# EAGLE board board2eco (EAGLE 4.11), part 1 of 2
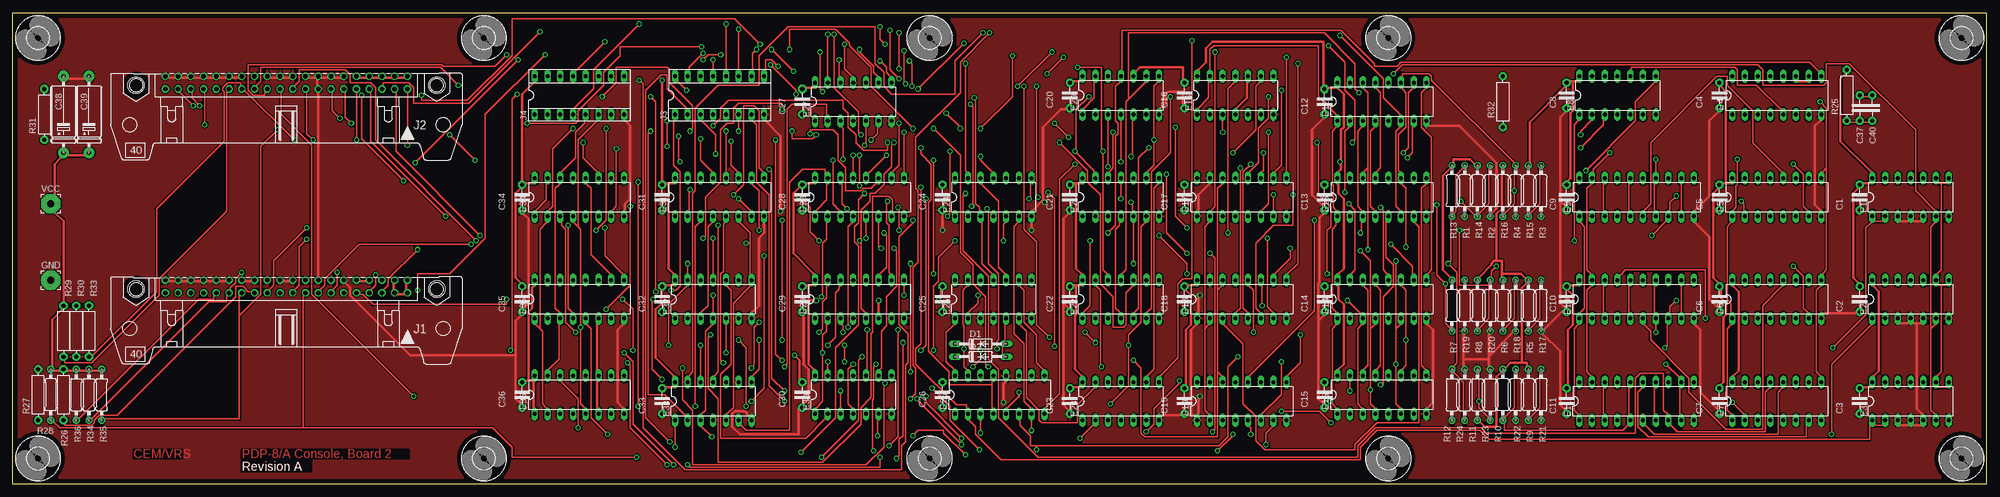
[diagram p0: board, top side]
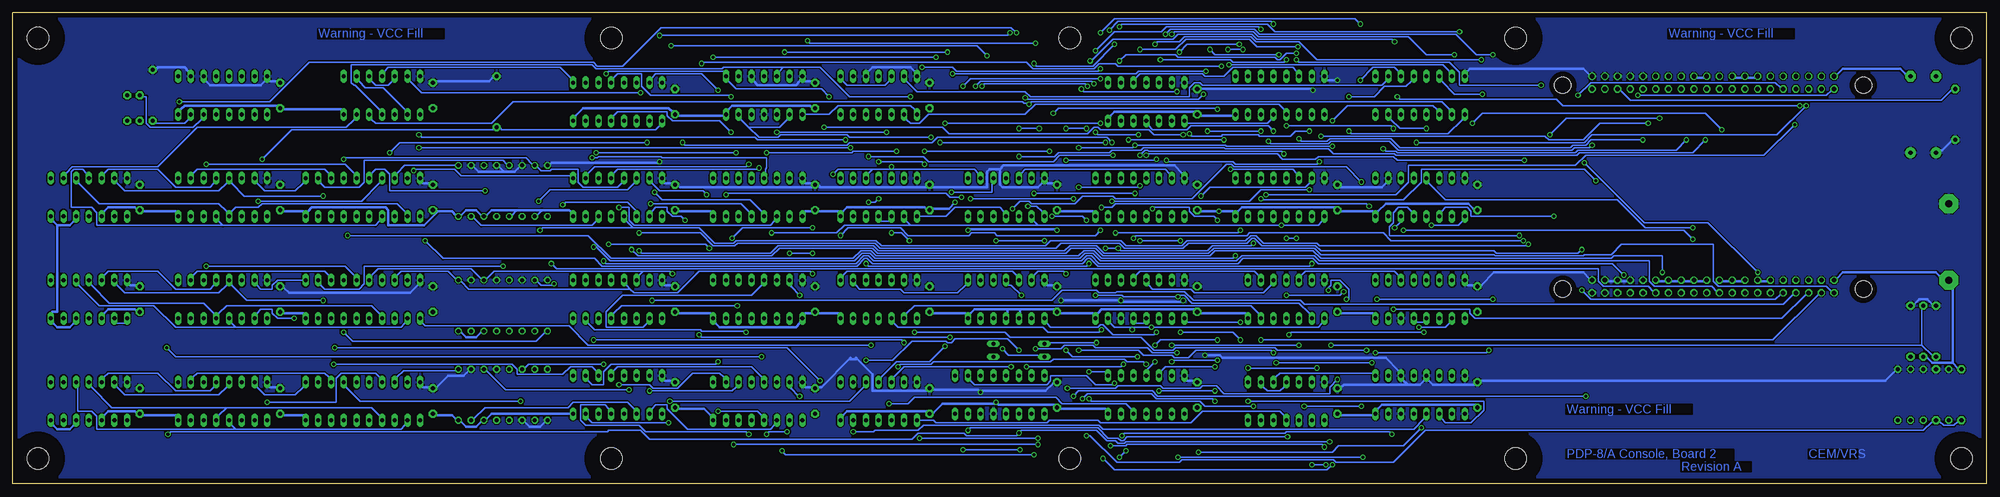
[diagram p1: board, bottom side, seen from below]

Size 393.7 x 93.98 mm. Coordinates in mm from the lower left corner, seen from the top.
Outline: 0,0 0,93.98 393.7,93.98 393.7,0 0,0
Copper layers (1*16): Top 0.035mm / dielectric 1.5mm / Bottom 0.035mm
Design rules "olimex8mil": minimum track width 10mil, minimum drill 24mil, track to track 8mil, track to pad 8mil, pad to pad 10mil, via to via 8mil, smd to smd 8mil, copper to edge 40mil, drill to drill 10mil, minimum pad ring 10mil, minimum via ring 8mil, stop-mask expansion 0mil, vias tented up to drill 0mil, thermal gap 10mil
Net classes: 1 Supply: width 0.508 mm

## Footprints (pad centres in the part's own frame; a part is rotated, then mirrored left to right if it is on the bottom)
C-5 = drill 0.813 pad 1.6 octagon: 1 -2.54,0; 2 2.54,0
E15-5 = drill 0.813 pad 2.159 round: + -7.62,0 | drill 0.813 pad 2.159 octagon: - 7.62,0
DO35-10 = drill 0.813 long: A 5.08,0; C -5.08,0
DIL14 = drill 0.813 long: 1 -7.62,-3.81; 2 -5.08,-3.81; 3 -2.54,-3.81; 4 0,-3.81; 5 2.54,-3.81; 6 5.08,-3.81; 7 7.62,-3.81; 8 7.62,3.81; 9 5.08,3.81; 10 2.54,3.81; 11 0,3.81; 12 -2.54,3.81; 13 -5.08,3.81; 14 -7.62,3.81
DIL16 = drill 0.813 long: 1 -8.89,-3.81; 2 -6.35,-3.81; 3 -3.81,-3.81; 4 -1.27,-3.81; 5 1.27,-3.81; 6 3.81,-3.81; 7 6.35,-3.81; 8 8.89,-3.81; 9 8.89,3.81; 10 6.35,3.81; 11 3.81,3.81; 12 1.27,3.81; 13 -1.27,3.81; 14 -3.81,3.81; 15 -6.35,3.81; 16 -8.89,3.81
DIL20 = drill 0.813 long: 1 -11.43,-3.81; 2 -8.89,-3.81; 3 -6.35,-3.81; 4 -3.81,-3.81; 5 -1.27,-3.81; 6 1.27,-3.81; 7 3.81,-3.81; 8 6.35,-3.81; 9 8.89,-3.81; 10 11.43,-3.81; 11 11.43,3.81; 12 8.89,3.81; 13 6.35,3.81; 14 3.81,3.81; 15 1.27,3.81; 16 -1.27,3.81; 17 -3.81,3.81; 18 -6.35,3.81; 19 -8.89,3.81; 20 -11.43,3.81
3,81/1,4 = drill 1.397 pad 3.81 octagon: 1 0,0
40H = drill 0.914 round: 1 -24.13,-1.27 | drill 0.914 octagon: 2 -24.13,1.27; 3 -21.59,-1.27; 4 -21.59,1.27; 5 -19.05,-1.27; 6 -19.05,1.27; 7 -16.51,-1.27; 8 -16.51,1.27; 9 -13.97,-1.27; 10 -13.97,1.27; 11 -11.43,-1.27; 12 -11.43,1.27; 13 -8.89,-1.27; 14 -8.89,1.27; 15 -6.35,-1.27; 16 -6.35,1.27; 17 -3.81,-1.27; 18 -3.81,1.27; 19 -1.27,-1.27; 20 -1.27,1.27; 21 1.27,-1.27; 22 1.27,1.27; 23 3.81,-1.27; 24 3.81,1.27; 25 6.35,-1.27; 26 6.35,1.27; 27 8.89,-1.27; 28 8.89,1.27; 29 11.43,-1.27; 30 11.43,1.27; 31 13.97,-1.27; 32 13.97,1.27; 33 16.51,-1.27; 34 16.51,1.27; 35 19.05,-1.27; 36 19.05,1.27; 37 21.59,-1.27; 38 21.59,1.27; 39 24.13,-1.27; 40 24.13,1.27 | hole 3.302: -29.972,0.533; 29.972,0.533
SOCKED-16 = drill 0.813 long: 1 -8.89,-3.81; 2 -6.35,-3.81; 3 -3.81,-3.81; 4 -1.27,-3.81; 5 1.27,-3.81; 6 3.81,-3.81; 7 6.35,-3.81; 8 8.89,-3.81; 9 8.89,3.81; 10 6.35,3.81; 11 3.81,3.81; 12 1.27,3.81; 13 -1.27,3.81; 14 -3.81,3.81; 15 -6.35,3.81; 16 -8.89,3.81
0207/10 = drill 0.813 octagon: 1 -5.08,0; 2 5.08,0
R-10 = drill 0.813 pad 1.6 octagon: 1 -5.08,0; 2 5.08,0
4,3 = hole 4.3: 0,0

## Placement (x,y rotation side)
C1  [C-5]  368.3,57.15 90 top
C2  [C-5]  368.3,36.83 90 top
C3  [C-5]  368.3,16.51 90 top
C4  [C-5]  340.36,77.47 90 top
C5  [C-5]  340.36,57.15 90 top
C6  [C-5]  340.36,36.83 90 top
C7  [C-5]  340.36,16.51 90 top
C8  [C-5]  309.88,77.47 90 top
C9  [C-5]  309.88,57.15 90 top
C10  [C-5]  309.88,36.83 90 top
C11  [C-5]  309.88,16.51 90 top
C12  [C-5]  261.62,76.2 90 top
C13  [C-5]  261.62,57.15 90 top
C14  [C-5]  261.62,36.83 90 top
C15  [C-5]  261.62,17.78 90 top
C16  [C-5]  233.68,77.47 90 top
C17  [C-5]  233.68,57.15 90 top
C18  [C-5]  233.68,36.83 90 top
C19  [C-5]  233.68,16.51 90 top
C20  [C-5]  210.82,77.47 90 top
C21  [C-5]  210.82,57.15 90 top
C22  [C-5]  210.82,36.83 90 top
C23  [C-5]  210.82,16.51 90 top
C24  [C-5]  185.42,57.15 90 top
C25  [C-5]  185.42,36.83 90 top
C26  [C-5]  185.42,17.78 90 top
C27  [C-5]  157.48,76.2 90 top
C28  [C-5]  157.48,57.15 90 top
C29  [C-5]  157.48,36.83 90 top
C30  [C-5]  157.48,17.78 90 top
C31  [C-5]  129.54,57.15 90 top
C32  [C-5]  129.54,36.83 90 top
C33  [C-5]  129.54,16.51 90 top
C34  [C-5]  101.6,57.15 90 top
C35  [C-5]  101.6,36.83 90 top
C36  [C-5]  101.6,17.78 90 top
C37  10  [C-5]  368.3,74.93 270 top
C38  6.8uf  [E15-5]  10.16,73.66 90 top
C39  6.8uf  [E15-5]  15.24,73.66 90 top
C40  47  [C-5]  370.84,74.93 270 top
D1  1N4148  [DO35-10]  193.04,27.94 0 top
D2  1N4148  [DO35-10]  193.04,25.4 0 top
E1  74LS95N  [DIL14]  378.46,57.15 0 top
E2  74LS95N  [DIL14]  378.46,36.83 0 top
E3  74LS95N  [DIL14]  378.46,16.51 0 top
E4  74LS123N  [DIL16]  351.79,77.47 0 top
E5  74LS175N  [DIL16]  351.79,57.15 0 top
E6  74LS175N  [DIL16]  351.79,36.83 0 top
E7  74LS175N  [DIL16]  351.79,16.51 0 top
E8  74LS00N  [DIL14]  320.04,77.47 0 top
E9  74S244N  [DIL20]  323.85,57.15 0 top
E10  74S244N  [DIL20]  323.85,36.83 0 top
E11  74S244N  [DIL20]  323.85,16.51 0 top
E12  74LS174N  [DIL16]  273.05,76.2 0 top
E13  74LS174N  [DIL16]  273.05,57.15 0 top
E14  74LS174N  [DIL16]  273.05,36.83 0 top
E15  74LS174N  [DIL16]  273.05,17.78 0 top
E16  74LS74N  [DIL14]  243.84,77.47 0 top
E17  74LS153N  [DIL16]  245.11,57.15 0 top
E18  74LS153N  [DIL16]  245.11,36.83 0 top
E19  74LS153N  [DIL16]  245.11,16.51 0 top
E20  74LS74N  [DIL14]  220.98,77.47 0 top
E21  74LS27N  [DIL14]  220.98,57.15 0 top
E22  74LS02N  [DIL14]  220.98,36.83 0 top
E23  7416N  [DIL14]  220.98,16.51 0 top
E24  74LS04N  [DIL14]  195.58,57.15 0 top
E25  74LS27N  [DIL14]  195.58,36.83 0 top
E26  74LS75N  [DIL16]  196.85,17.78 0 top
E27  7404N  [DIL14]  167.64,76.2 0 top
E28  74LS367N  [DIL16]  168.91,57.15 0 top
E29  74LS138N  [DIL16]  168.91,36.83 0 top
E30  74LS00N  [DIL14]  167.64,17.78 0 top
E31  74LS367N  [DIL16]  140.97,57.15 0 top
E32  74LS08N  [DIL14]  139.7,36.83 0 top
E33  74LS02N  [DIL14]  139.7,16.51 0 top
E34  74LS367N  [DIL16]  113.03,57.15 0 top
E35  74LS138N  [DIL16]  113.03,36.83 0 top
E36  74LS174N  [DIL16]  113.03,17.78 0 top
GND  [3,81/1,4]  7.62,40.64 0 top
J1  [40H]  54.61,39.37 180 top
J2  [40H]  54.61,80.01 180 top
J3  [SOCKED-16]  140.97,77.47 0 top
J4  [SOCKED-16]  113.03,77.47 0 top
R1  680  [0207/10]  289.56,58.42 90 top
R2  680  [0207/10]  294.64,58.42 90 top
R3  680  [0207/10]  304.8,58.42 90 top
R4  680  [0207/10]  299.72,58.42 90 top
R5  330  [0207/10]  302.26,35.56 90 top
R6  330  [0207/10]  297.18,35.56 90 top
R7  330  [0207/10]  287.02,35.56 90 top
R8  330  [0207/10]  292.1,35.56 90 top
R9  330  [0207/10]  302.26,17.78 90 top
R10  330  [0207/10]  297.18,17.78 90 top
R11  330  [0207/10]  292.1,17.78 270 top
R12  330  [0207/10]  287.02,17.78 270 top
R13  330  [0207/10]  287.02,58.42 90 top
R14  330  [0207/10]  292.1,58.42 90 top
R15  330  [0207/10]  302.26,58.42 90 top
R16  330  [0207/10]  297.18,58.42 90 top
R17  680  [0207/10]  304.8,35.56 90 top
R18  680  [0207/10]  299.72,35.56 90 top
R19  680  [0207/10]  289.56,35.56 90 top
R20  680  [0207/10]  294.64,35.56 90 top
R21  680  [0207/10]  304.8,17.78 90 top
R22  680  [0207/10]  299.72,17.78 90 top
R23  680  [0207/10]  294.64,17.78 270 top
R24  680  [0207/10]  289.56,17.78 270 top
R25  6K8  [R-10]  365.76,77.47 90 top
R26  180  [R-10]  10.16,17.78 270 top
R27  390  [R-10]  5.08,17.78 90 top
R28  1K  [0207/10]  7.62,17.78 90 top
R29  180  [R-10]  10.16,30.48 270 top
R30  390  [R-10]  12.7,30.48 270 top
R31  1K  [R-10]  6.35,73.66 90 top
R32  1K  [R-10]  297.18,76.2 270 top
R33  1K  [R-10]  15.24,30.48 270 top
R34  1K  [0207/10]  15.24,17.78 270 top
R35  1K  [0207/10]  17.78,17.78 270 top
R36  1K  [0207/10]  12.7,17.78 270 top
U$11  [4,3]  93.98,88.9 0 top
U$12  [4,3]  5.08,88.9 0 top
U$13  [4,3]  182.88,88.9 0 top
U$14  [4,3]  274.32,88.9 0 top
U$15  [4,3]  388.62,88.9 0 top
U$16  [4,3]  388.62,5.08 0 top
U$17  [4,3]  274.32,5.08 0 top
U$18  [4,3]  182.88,5.08 0 top
U$19  [4,3]  93.98,5.08 0 top
U$20  [4,3]  5.08,5.08 0 top
VCC  [3,81/1,4]  7.62,55.88 0 top

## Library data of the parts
C1-C37 C40 R25-R27 R29-R33 = discrete
C38 C39 R1-R24 R28 R34-R36 = rcl
D1 D2 = diode
E1-E36 = 74xx-us
GND VCC = wirepad
J1 J2 = con-harting-h
J3 J4 = ic-package
U$11-U$20 = holes

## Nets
ADDR0: E18.9 J3.9
ADDR1: E17.7 J3.12
ADDR2: E17.9 J3.10
ADRLTH\: E8.11 E12.9 E14.9
BEMA0: E27.10 J3.14
BEMA1: E27.8 J3.15
BEMA2: E27.12 J3.13
BFSW\: E28.9 J2.24
BKDTACNTL\: E28.3 J2.12
BOOTF\: E16.2 E16.6 E28.10
BPOK: E5.1 E6.1 E7.1 E12.1 E13.1 E14.1 E15.1 E16.1 E16.13 E20.1 E20.13 E23.10 J4.10 R32.2
BRUN: E24.6 E26.7 E32.4 E33.3 J4.12
BUS0: E11.3 E11.18 E14.3 E15.3 J1.34 R9.1 R21.2
BUS1: E10.3 E10.18 E14.13 E15.13 J1.36 R5.1 R17.2
BUS2: E9.3 E9.18 E12.6 E13.6 J1.38 R3.2 R15.1
BUS3: E11.5 E11.16 E14.4 E15.4 J1.40 R10.1 R22.2
BUS4: E10.5 E10.16 E14.14 E15.14 J1.20 R6.1 R18.2
BUS5: E9.5 E9.16 E12.11 E13.11 J1.22 R4.2 R16.1
BUS6: E11.7 E11.14 E14.6 E15.6 J1.8 R11.1 R23.2
BUS7: E10.7 E10.14 E12.3 E13.3 J1.6 R7.1 R19.2
BUS8: E9.7 E9.14 E12.13 E13.13 J1.12 R1.2 R12.1 R13.1 R24.2
BUS9: E11.9 E11.12 E14.11 E15.11 J1.10
BUS10: E10.9 E10.12 E12.4 E13.4 J1.16 R8.1 R20.2
BUS11: E9.9 E9.12 E12.14 E13.14 J1.14 R2.2 R14.1
BUSEN\: E34.13 J1.24
DEP\: E28.5 J2.20
DISP0: E34.14 E35.3 E36.15 J4.5
DISP1: E34.4 E35.2 E36.5 J4.6
DISP2: E34.2 E35.1 E36.2 J4.7
DISPINH: E16.9 E22.12 J4.4
DISPLAY0: E19.7 J3.7
DISPLAY1: E19.9 J3.11
DISPLAY2: E18.7 J3.6
DSPLTH\: E8.8 E13.9 E15.9
E30PIN8: E21.5 E21.11 E30.8
E35-Y4: E32.12 E35.11
EMA0\: E27.11 J1.30 R34.2
EMA1\: E27.9 J1.28 R35.2
EMA2\: E27.13 J1.32 R36.2
EMODE\: E1.6 E2.6 E3.6 E16.8 E22.6
ENT0: E3.13 E7.13 E11.8 E36.14
ENT1: E2.13 E6.13 E10.8 E36.4
ENT2: E1.13 E5.13 E9.8 E36.3
EXTPUL\: J4.9
FUN\: E24.3 E25.2 E25.11 J4.15
GATEENT\: E9.1 E10.1 E11.1 E21.6 E30.5
GATESR\: E9.19 E10.19 E11.19 E32.11
GND [Supply]: C1.1 C2.1 C3.1 C4.1 C5.1 C6.1 C7.1 C8.1 C9.1 C10.1 C11.1 C12.1 C13.1 C14.1 C15.1 C16.1 C17.1 C18.1 C19.1 C20.1 C21.1 C22.1 C23.1 C24.1 C25.1 C26.1 C27.1 C28.1 C29.1 C30.1 C31.1 C32.1 C33.1 C34.1 C35.1 C36.1 C38.- C39.- E1.3 E1.4 E1.5 E1.7 E2.3 E2.4 E2.5 E2.7 E3.3 E3.4 E3.5 E3.7 E4.8 E5.8 E6.8 E7.8 E8.7 E9.10 E10.10 E11.10 E12.8 E13.8 E14.8 E15.8 E16.7 E17.1 E17.8 E17.15 E18.1 E18.8 E18.15 E19.1 E19.8 E19.15 E20.7 E21.7 E22.7 E23.7 E24.7 E25.3 E25.4 E25.7 E26.12 E27.7 E28.8 E29.8 E30.7 E31.8 E32.7 E33.7 E34.8 E35.8 E36.8 GND.1 J1.11 J1.13 J1.15 J1.17 J1.19 J1.21 J1.23 J1.25 J1.27 J1.29 J1.31 J1.33 J1.35 J1.37 J1.39 J2.11 J2.13 J2.15 J2.16 J2.17 J2.19 J2.21 J2.23 J2.25 J2.27 J2.29 J2.31 J2.33 J2.35 J2.37 J2.39 J3.8 J4.8 R1.1 R2.1 R3.1 R4.1 R17.1 R18.1 R19.1 R20.1 R21.1 R22.1 R23.1 R24.1 R27.2 R30.2
IND1\: E28.7 E34.3 J2.8
IND2\: E34.5 J2.4
INIT\: E31.9 J2.34
KEY-F\: E26.4 E26.13 E27.5 J4.3
KEYCNTL\: E31.13 J2.10
KEYSTB: E8.5 E24.1 J4.2
KEYSTB\: E16.11 E21.2 E24.2 E31.1 E33.9 E33.11
KFUN0\: E3.1 E3.2 E26.2 J3.3
KFUN1\: E2.1 E2.2 E26.3 J3.2
KFUN2\: E1.1 E1.2 E26.6 J3.1
LAENAB\: E23.2 J2.22
LDSR: E5.9 E6.9 E7.9 E33.13
MAEN\: E23.8 J2.32
MALC\: E28.11 J2.36
MCLOCK\: E33.2 J4.1
MD\: E34.7 J2.18
MEMSTART\: E23.12 J2.26
MH0: E8.13 E20.9 E22.11
MH0\: E8.2 E8.9 E20.8 E20.12 E21.9
MPXA: E17.14 E18.14 E19.14 J4.14
MPXB: E17.2 E18.2 E19.2 J4.13
MSIRDIS\: E31.11 J2.2
N$1: E2.12 E6.12 E10.6
N$2: E1.12 E5.12 E9.6
N$3: E1.10 E5.4 E9.2
N$4: E1.11 E5.5 E9.4
N$5: E2.10 E6.4 E10.2
N$6: E2.11 E6.5 E10.4
N$7: E3.12 E7.12 E11.6
N$8: E3.10 E7.4 E11.2
N$9: E3.11 E7.5 E11.4
N$10: E15.2 E19.3
N$11: E15.5 E19.5
N$12: E15.7 E19.4
N$13: E15.10 E19.6
N$14: E15.12 E19.13
N$15: E15.15 E19.11
N$16: E13.2 E19.12
N$17: E13.5 E19.10
N$18: E13.7 E18.3
N$19: E13.10 E18.5
N$20: E13.12 E18.4
N$21: E13.15 E18.6
N$22: E14.2 E18.13
N$23: E14.5 E18.11
N$24: E14.7 E18.12
N$25: E14.10 E18.10
N$26: E12.15 E17.10
N$27: E12.12 E17.12
N$28: E12.10 E17.11
N$29: E12.7 E17.13
N$30: E14.15 E17.5
N$31: E14.12 E17.3
N$32: E12.2 E17.4
N$33: E12.5 E17.6
N$34: E16.3 E21.12
N$35: E21.1 E24.4
N$36: E22.10 E29.4 E29.5 E31.15
N$37: E22.13 E30.4
N$38: E8.3 E22.5
N$39: E22.3 E33.1
N$40: E22.2 E32.6
N$41: E4.9 E20.11 E22.1
N$42: E22.8 E25.12
N$43: D1.C E31.5
N$44: E24.8 E32.5
N$45: D2.C E31.3
N$46: E33.10 E36.9
N$47: E23.11 E24.10
N$48: E29.15 E33.8
N$49: E26.10 E29.1
N$50: E25.13 E26.15 E27.3 E29.2 E30.1
N$51: E25.1 E26.16 E29.3
N$52: E21.3 E21.4 E22.4
N$53: E22.9 E25.8
N$54: D1.A D2.A E25.5
N$55: E28.4 E29.7 E30.10 E32.1
N$56: E28.2 E29.9 E32.2
N$57: E29.10 E31.2
N$58: E29.11 E31.10
N$59: E29.12 E32.9
N$60: E29.13 E30.2 E32.10
N$61: E29.14 E33.12
N$62: E23.1 E33.4
N$63: E7.15 E11.11
N$64: E7.10 E11.13
N$65: E7.7 E11.15
N$66: E7.2 E11.17
N$67: E27.6 E30.13
N$68: E28.14 E30.11
N$69: E31.4 E32.3
N$70: E30.6 E34.1 E34.15 E35.4 E35.5
N$71: E28.6 E30.9 E31.6 E32.8 E33.5
N$72: E34.12 E35.10
N$73: E34.6 E35.9
N$74: E27.4 E31.12
N$75: E4.5 E8.10 E8.12
N$76: E30.3 E31.14
N$77: E27.2 E30.12
N$78: E23.13 E25.6
N$79: E6.15 E10.11
N$80: E6.10 E10.13
N$81: E6.7 E10.15
N$82: E6.2 E10.17
N$83: E5.15 E9.11
N$84: E5.10 E9.13
N$85: E5.2 E9.17
N$86: E5.7 E9.15
N$87: E21.8 E23.9
N$88: C37.1 C40.1 E4.6
N$89: C37.2 C40.2 E4.7 R25.1
N$93: E20.4 E26.8
N$94: E25.9 E26.9
NUM: E8.4 E16.12 E21.13 J4.11
NUMCLK: E1.8 E1.9 E2.8 E2.9 E3.8 E3.9 E8.6
PANLOCK: E24.12 E25.10 E28.1 E28.15 E33.6
PANLOCK\: E24.13 J2.6 R31.2
POWCK: E24.11 J2.28 R33.2
PULSELOADADD\: E31.7 J2.40
RUN\: E24.5 J1.18 R28.1
SHLT\: E27.1 J3.5
SINGSTEP\: E28.13 J2.14
SRDATA\: E8.1 E32.13 J2.30 R29.2 R30.1
STATE\: E34.11 J2.38
STHIS\: E20.2 J3.4
THIS: E20.5 E28.12
TS1\: E20.3 E21.10 E24.9 J1.26 R26.2 R27.1
VCC [Supply]: C1.2 C2.2 C3.2 C4.2 C5.2 C6.2 C7.2 C8.2 C9.2 C10.2 C11.2 C12.2 C13.2 C14.2 C15.2 C16.2 C17.2 C18.2 C19.2 C20.2 C21.2 C22.2 C23.2 C24.2 C25.2 C26.2 C27.2 C28.2 C29.2 C30.2 C31.2 C32.2 C33.2 C34.2 C35.2 C36.2 C38.+ C39.+ E1.14 E2.14 E3.14 E4.10 E4.11 E4.16 E5.16 E6.16 E7.16 E8.14 E9.20 E10.20 E11.20 E12.16 E13.16 E14.16 E15.16 E16.4 E16.10 E16.14 E17.16 E18.16 E19.16 E20.10 E20.14 E21.14 E22.14 E23.14 E24.14 E25.14 E26.5 E27.14 E28.16 E29.6 E29.16 E30.14 E31.16 E32.14 E33.14 E34.10 E34.16 E35.6 E35.16 E36.1 E36.6 E36.11 E36.13 E36.16 J1.1 J1.2 J1.3 J1.4 J1.5 J1.7 J1.9 J2.1 J2.3 J2.5 J2.7 J2.9 J3.16 J4.16 R5.2 R6.2 R7.2 R8.2 R9.2 R10.2 R11.2 R12.2 R13.2 R14.2 R15.2 R16.2 R25.2 R26.1 R28.2 R29.1 R31.1 R32.1 R33.1 R34.1 R35.1 R36.1 VCC.1

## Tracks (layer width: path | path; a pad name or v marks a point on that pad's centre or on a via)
ADDR0  (via drill 0.61)
  Top 0.254: v256.29,83.82 256.29,43.94 254.25,41.91 E18.9 | v152.65,83.31 151.38,84.58 150.11,84.58 150.11,82.55 J3.9
  Bottom 0.254: v256.29,83.82 256.03,84.07 191.52,84.07 190.25,82.8 178.05,82.8 177.04,83.82 173.74,83.82 173.23,83.31 v152.65,83.31
ADDR1  (via drill 0.61)
  Top 0.254: v251.46,57.66 251.46,54.61 E17.7 | v204.47,57.15 204.22,57.4 v204.22,79.25 | v176.78,80.77 175.01,82.55 v175.01,90.42 | v142.24,91.69 142.24,82.55 J3.12
  Bottom 0.254: v251.46,57.66 251.21,57.91 207.52,57.91 206.76,57.15 v204.47,57.15 | v204.22,79.25 202.69,80.77 v176.78,80.77 | v175.01,90.42 173.23,92.2 142.75,92.2 v142.24,91.69
ADDR2  (via drill 0.61)
  Top 0.254: v254,85.09 254,62.23 E17.9 | v206.25,81.79 v209.55,85.09 | v155.7,82.3 v151.38,86.61 | v148.34,86.61 147.57,85.85 147.57,82.55 J3.10
  Bottom 0.254: v209.55,85.09 v254,85.09 | v206.25,81.79 169.67,81.79 169.16,82.3 v155.7,82.3 | v151.38,86.61 v148.34,86.61
ADRLTH\
  Top 0.254: E14.9 282.19,41.91 282.96,42.67 282.96,69.09 280.92,71.12 280.92,77.98 281.69,78.74 E12.9
  Bottom 0.254: E8.11 319.53,82.3 318.77,83.06 284.48,83.06 282.45,81.03 E12.9
BEMA0
  Bottom 0.254: E27.10 169.67,81.03 168.91,81.79 156.46,81.79 155.96,81.28 152.15,81.28 150.37,83.06 138.43,83.06 137.67,82.3 J3.14
BEMA1  (via drill 0.61)
  Top 0.254: v172.97,84.33 174.24,83.06 174.24,82.04 175.01,81.28 E27.8 | v137.67,85.85 134.87,83.06 134.87,82.55 J3.15
  Bottom 0.254: v172.97,84.33 171.7,85.6 161.8,85.6 161.29,85.09 141.99,85.09 141.48,84.58 140.97,84.58 139.7,85.85 v137.67,85.85
BEMA2  (via drill 0.61)
  Top 0.254: v139.7,84.58 139.7,82.55 J3.13 | v164.85,84.58 164.85,81.28 E27.12
  Bottom 0.254: v139.7,84.58 140.21,84.07 150.37,84.07 150.88,84.58 v164.85,84.58
BFSW\  (via drill 0.61)
  Top 0.254: v177.8,70.1 177.8,62.23 E28.9 | v169.16,69.6 168.66,70.1 168.66,74.17 163.83,78.99 v163.83,89.66 | v98.55,85.6 96.27,83.31 85.85,83.31 85.6,83.57 46.99,83.57 46.99,78.49 48.01,77.47 50.29,77.47 50.29,78.49 J2.24
  Bottom 0.254: v177.8,70.1 177.29,69.6 v169.16,69.6 | v163.83,89.66 162.81,90.68 146.05,90.68 145.03,89.66 105.92,89.66 101.85,85.6 v98.55,85.6
BKDTACNTL\  (via drill 0.61)
  Top 0.254: v163.58,64.52 163.58,55.88 164.85,54.61 E28.3 | v133.1,64.26 132.84,64.52 v132.84,69.34 | v67.56,71.88 66.29,73.15 66.29,78.23 J2.12
  Bottom 0.254: v163.58,64.52 163.32,64.26 150.37,64.26 149.86,63.75 133.6,63.75 v133.1,64.26 | v132.84,69.34 88.14,69.34 87.38,68.58 80.52,68.58 77.22,71.88 v67.56,71.88
BOOTF\  (via drill 0.61)
  Top 0.254: v176.78,71.88 176.78,63.5 175.51,62.23 E28.10 | v210.57,69.09 v207.77,71.88
  Bottom 0.254: v207.77,71.88 v176.78,71.88 | v210.57,69.09 226.82,69.09 227.33,69.6 240.54,69.6 241.05,69.09 244.86,69.09 246.89,71.12 | 246.89,71.12 248.41,72.64 E16.6 | 246.89,71.12 240.79,71.12 239.27,72.64 E16.2
BPOK  (via drill 0.61)
  Top 0.254: E16.1 236.47,74.93 238.51,76.96 238.51,80.01 E16.13 238.76,82.55 238.76,86.61 239.52,87.38 260.35,87.38 260.35,77.22 263.91,73.66 E12.1 263.91,71.12 263.14,70.36 263.14,59.69 263.4,59.44 263.4,55.12 263.91,54.61 E13.1 263.91,52.07 263.91,51.56 263.14,50.8 263.14,35.05 263.91,34.29 E14.1 263.91,31.75 263.14,30.99 263.14,16.51 | E20.1 213.61,74.93 215.65,76.96 215.65,80.01 E20.13 | 263.14,16.51 263.14,16 263.91,15.24 E15.1 | 263.14,16.51 v262.64,16.51 | E7.1 342.65,13.97 341.88,14.73 341.88,30.99 342.65,31.75 E6.1 342.65,34.29 342.65,36.07 341.88,36.83 341.88,51.31 342.65,52.07 E5.1 343.15,54.61 343.66,55.12 343.66,59.44 343.92,59.69 v343.92,64.77
  Bottom 0.254: J4.10 119.89,80.26 120.65,79.5 156.46,79.5 156.97,80.01 157.99,80.01 159,78.99 159,77.22 190.75,77.22 191.77,78.23 213.36,78.23 215.39,80.26 E20.13 | E16.1 235.71,73.66 230.89,73.66 229.11,75.44 214.63,75.44 213.87,74.68 E20.1 | v262.64,16.51 226.82,16.51 224.03,19.3 E23.10 | E12.1 264.67,71.37 265.43,70.61 296.16,70.61 296.42,70.87 R32.2 297.69,70.61 338.07,70.61 v343.92,64.77
BRUN  (via drill 0.61)
  Top 0.254: E24.6 200.41,52.07 199.64,51.31 199.64,29.97 201.68,27.94 201.68,16.51 202.95,15.24 E26.7 203.2,12.7 v203.2,10.67 | v127.25,77.22 128.27,76.2 v128.27,38.35 | v139.7,37.59 139.7,34.29 E32.4 139.45,31.75 138.18,30.48 138.18,14.73 137.41,13.97 E33.3 137.41,11.43 v139.45,9.4
  Bottom 0.254: v127.25,77.22 122.17,77.22 120.14,79.25 115.82,79.25 114.81,80.26 J4.12 | v128.27,38.35 129.03,37.59 v139.7,37.59 | v203.2,10.67 202.69,11.18 177.29,11.18 175.26,9.14 173.23,9.14 172.72,8.64 172.21,8.64 171.45,9.4 v139.45,9.4
BUS0  (via drill 0.61)
  Top 0.254: E11.3 317.25,13.97 317.25,19.05 E11.18 | R9.1 302.51,13.21 304.55,15.24 304.55,22.35 R21.2 | E15.3 268.99,15.24 268.22,16 268.22,30.99 268.99,31.75 E14.3 268.73,34.04 v266.19,36.58
  Bottom 0.254: E11.18 316.99,21.34 315.72,22.61 305.31,22.61 R21.2 | v266.19,36.58 186.44,36.58 184.4,38.61 177.55,38.61 177.04,38.1 173.74,38.1 173.48,38.35 160.02,38.35 158.24,36.58 136.91,36.58 136.14,35.81 40.64,35.81 38.61,37.85 J1.34 | R9.1 301.75,12.95 299.47,15.24 282.96,15.24 281.94,16.26 271.02,16.26 269.75,14.99 E15.3
BUS1  (via drill 0.61)
  Top 0.254: E10.3 317.25,34.29 317.25,39.37 E10.18 | R5.1 302.51,30.99 304.55,33.02 304.55,40.13 R17.2 | E15.13 272.03,22.86 272.8,23.62 272.8,38.61 272.03,39.37 E14.13 | v118.36,34.8 123.19,39.62 v123.19,55.37 | v176.53,55.12 176.78,54.86 v176.78,50.55 | v228.6,49.53 234.19,43.94 v234.19,41.91
  Bottom 0.254: E10.18 316.99,41.66 316.23,42.42 306.83,42.42 305.31,40.89 R17.2 304.29,40.39 302.77,38.86 270.51,38.86 | v118.36,34.8 103.12,34.8 103.12,34.04 102.11,33.02 40.89,33.02 36.07,37.85 J1.36 | v123.19,55.37 123.7,55.88 173.74,55.88 174.5,55.12 v176.53,55.12 | v176.78,50.55 177.8,49.53 197.36,49.53 197.87,50.04 202.44,50.04 202.95,49.53 215.14,49.53 216.66,51.05 227.08,51.05 v228.6,49.53 | v234.19,41.91 234.7,42.42 256.79,42.42 261.11,38.1 269.75,38.1 270.51,38.86 | 270.51,38.86 271.27,39.62 E14.13
BUS2  (via drill 0.61)
  Top 0.254: E9.3 317.25,54.61 317.25,59.69 E9.18 | R15.1 302.51,53.85 304.55,55.88 304.55,62.99 R3.2 | E13.6 276.61,54.61 275.84,55.37 275.84,70.36 276.61,71.12 E12.6 276.61,73.66 273.3,76.96 273.3,80.77 v264.67,89.41 | v144.78,28.7 146.3,27.18 v146.3,15.49 | v179.07,17.02 180.09,18.03 180.09,23.11 179.58,23.62 179.58,43.18 180.59,44.2 180.59,58.42 180.09,58.93 180.09,69.09 188.98,77.98 188.98,84.07 v194.82,89.92
  Bottom 0.254: E9.18 316.99,61.98 315.47,63.5 305.31,63.5 R3.2 | v144.78,28.7 42.67,28.7 33.53,37.85 J1.38 | v146.3,15.49 155.96,15.49 156.97,16.51 178.56,16.51 v179.07,17.02 | v194.82,89.92 195.33,89.41 v264.67,89.41 | R15.1 301.75,53.09 300.23,51.56 278.13,51.56 277.37,52.32 E13.6
BUS3  (via drill 0.61)
  Top 0.254: E11.16 322.33,19.05 322.33,13.97 E11.5 322.07,11.68 321.06,10.67 297.43,10.67 297.43,12.19 R10.1 297.43,13.21 299.47,15.24 299.47,22.35 R22.2 | 270.76,30.99 v270.76,18.8 270.76,16 271.53,15.24 E15.4 | 270.76,30.99 271.53,31.75 E14.4 | v268.73,46.48 270.76,44.45 270.76,30.99
  Bottom 0.254: v268.73,46.48 268.22,45.97 242.57,45.97 241.05,47.5 222,47.5 220.98,46.48 183.9,46.48 182.88,47.5 177.55,47.5 176.02,45.97 155.19,45.97 154.18,46.99 134.11,46.99 132.84,45.72 98.3,45.72 98.04,45.47 80.52,45.47 80.26,45.72 74.93,45.72 72.9,47.75 54.61,47.75 54.61,40.39 53.59,39.37 32,39.37 30.99,38.35 J1.40 | v270.76,18.8 295.4,18.8 299.21,22.61 R22.2
BUS4  (via drill 0.61)
  Top 0.254: E10.5 322.33,34.29 322.33,39.37 E10.16 | R6.1 297.43,30.99 299.47,33.02 299.47,40.13 R18.2 | E15.14 269.49,22.86 270.26,23.62 270.26,38.61 269.49,39.37 E14.14 | v58.67,48.77 57.15,47.24 57.15,39.62 56.13,38.61 J1.20 | v116.33,50.55 118.36,52.58 v118.36,70.87 | v139.7,71.37 141.22,72.9 141.22,74.93 142.75,76.45 165.61,76.45 165.61,74.93 166.62,73.91 166.62,71.12 168.15,69.6 168.15,68.07 169.67,66.55 174.5,66.55 v174.5,68.07 | v260.1,68.07 260.35,67.82 260.35,57.66 262.89,55.12 262.89,51.31 262.13,50.55 v262.13,41.91
  Bottom 0.254: E10.16 322.07,41.66 320.8,42.93 302.26,42.93 300.23,40.89 R18.2 299.21,40.89 297.69,42.42 267.97,42.42 | v58.67,48.77 60.45,50.55 v116.33,50.55 | v118.36,70.87 118.87,71.37 v139.7,71.37 | v174.5,68.07 175.51,69.09 209.3,69.09 210.31,68.07 226.82,68.07 227.33,67.56 259.59,67.56 v260.1,68.07 | v262.13,41.91 262.64,42.42 267.97,42.42 | 267.97,42.42 268.73,41.66 E14.14
BUS5  (via drill 0.61)
  Top 0.254: E9.5 322.33,54.61 322.33,59.69 E9.16 | R16.1 297.43,53.85 299.47,55.88 v299.47,58.42 299.47,62.99 R4.2 299.47,64.01 282.96,80.52 282.96,81.28 282.45,81.79 277.11,81.79 277.11,81.28 E12.11 277.11,78.74 277.88,77.98 277.88,71.12 276.35,69.6 276.35,62.48 276.61,62.23 E13.11 277.11,59.69 277.88,58.93 v277.88,47.24
  Bottom 0.254: v299.47,58.42 318.52,58.42 318.52,61.72 319.53,62.74 321.31,62.74 322.07,61.98 E9.16 | v277.88,47.24 277.37,47.24 274.57,44.45 225.81,44.45 224.28,45.97 222.76,45.97 221.74,44.96 180.85,44.96 179.83,45.97 178.31,45.97 176.78,44.45 149.61,44.45 148.59,45.47 134.11,45.47 133.1,44.45 67.31,44.45 67.31,40.39 66.29,39.37 54.86,39.37 53.85,38.35 J1.22
BUS6  (via drill 0.61)
  Top 0.254: E11.7 327.41,13.97 327.41,19.05 E11.14 | R23.2 294.39,13.21 292.35,15.24 v292.35,16.51 292.35,22.35 R11.1 | 275.84,30.99 v275.84,23.88 275.84,16 276.61,15.24 E15.6 | 275.84,30.99 276.61,31.75 E14.6 | v72.39,41.66 72.39,39.62 71.37,38.61 J1.8 | v275.84,44.45 275.84,30.99
  Bottom 0.254: v292.35,16.51 324.36,16.51 327.15,19.3 E11.14 | v72.39,41.66 74.68,43.94 133.35,43.94 134.37,44.96 148.34,44.96 149.35,43.94 177.04,43.94 178.56,45.47 179.58,45.47 180.59,44.45 222,44.45 223.01,45.47 224.03,45.47 225.55,43.94 275.34,43.94 v275.84,44.45 | v275.84,23.88 290.83,23.88 291.59,23.11 R11.1
BUS7  (via drill 0.61)
  Top 0.254: E10.14 327.41,39.37 327.41,34.29 E10.7 327.66,31.75 v327.66,30.23 | R7.1 286.77,30.99 285.75,32 v285.75,39.88 285.5,40.13 283.97,41.66 v283.97,55.63 | E12.3 268.99,71.12 268.22,70.36 268.22,55.37 268.99,54.61 E13.3 268.99,52.07 268.99,50.29 v268.73,50.04 | v80.77,46.74 74.93,40.89 74.93,39.62 73.91,38.61 J1.6
  Bottom 0.254: v285.75,39.88 286,39.62 288.29,39.62 289.05,40.39 R19.2 | v327.66,30.23 325.88,28.45 289.31,28.45 287.53,30.23 R7.1 | v80.77,46.74 81.53,45.97 97.79,45.97 98.3,46.48 132.84,46.48 133.86,47.5 144.53,47.5 146.05,49.02 146.56,49.02 147.57,48.01 159.26,48.01 160.27,46.99 171.96,46.99 172.97,48.01 184.66,48.01 185.67,46.99 220.73,46.99 221.74,48.01 249.17,48.01 249.68,47.5 254,47.5 256.54,50.04 v268.73,50.04 | v283.97,55.63 283.46,56.13 271.02,56.13 269.49,54.61 E13.3
BUS8  (via drill 0.61)
  Top 0.254: E13.13 272.03,62.23 272.8,62.99 272.8,77.98 272.03,78.74 E12.13 | R24.2 289.31,13.21 289.31,20.32 287.27,22.35 R12.1 287.27,23.37 288.04,24.13 288.04,42.16 286.51,43.69 v286.26,43.94 286.77,44.45 286.77,52.83 R13.1 287.27,53.85 287.78,54.36 287.78,61.47 289.31,62.99 R1.2 | E9.7 327.41,54.61 327.41,59.69 E9.14 327.66,62.23 v327.66,64.77
  Bottom 0.254: v286.26,43.94 285.24,42.93 77.47,42.93 77.47,40.39 76.45,39.37 67.56,39.37 66.55,38.35 J1.12 | v327.66,64.77 327.41,65.02 291.34,65.02 290.07,63.75 R1.2 289.05,63.25 288.29,62.48 286.51,62.48 286.26,62.74 280.92,62.74 280.92,60.2 279.91,59.18 273.05,59.18 272.29,59.94 E13.13
BUS9  (via drill 0.61)
  Top 0.254: E11.9 332.49,13.97 332.49,19.05 E11.12 332.23,21.34 v329.69,23.88 | E14.11 277.11,39.37 277.88,38.61 v277.88,28.7 277.88,23.62 277.11,22.86 E15.11 | v98.55,36.83 98.55,35.81 71.88,35.81 69.85,37.85 69.09,37.85 J1.10 | v121.67,36.83 123.7,34.8 v123.7,26.67 | v215.9,28.19 v213.87,30.23
  Bottom 0.254: v329.69,23.88 294.13,23.88 293.12,22.86 293.12,21.84 283.97,21.84 282.45,23.37 278.13,23.37 277.37,22.61 E15.11 | v121.67,36.83 v98.55,36.83 | v123.7,26.67 141.48,26.67 141.99,27.18 161.8,27.18 162.31,26.67 166.12,26.67 168.66,29.21 194.82,29.21 195.83,30.23 v213.87,30.23 | v215.9,28.19 216.41,28.7 v277.88,28.7
BUS10  (via drill 0.61)
  Top 0.254: E10.9 332.74,34.29 332.74,39.37 E10.12 | 294.39,39.62 294.39,40.13 R20.2 294.89,41.15 294.89,42.42 v295.91,43.43 | 294.39,39.62 294.39,33.02 292.35,30.99 R8.1 | E13.4 271.53,54.61 270.76,55.37 270.76,70.36 271.53,71.12 E12.4 | v91.44,47.75 69.09,47.75 62.23,40.89 62.23,39.62 61.21,38.61 J1.16 | 294.39,39.62 288.54,39.62 v288.54,50.55
  Bottom 0.254: v295.91,43.43 323.6,43.43 323.6,39.88 324.61,38.86 331.47,38.86 332.23,39.62 E10.12 | v91.44,47.75 91.69,47.5 133.1,47.5 133.6,48.01 144.27,48.01 145.8,49.53 146.81,49.53 147.83,48.51 159.51,48.51 160.53,47.5 171.7,47.5 172.72,48.51 186.69,48.51 187.71,47.5 220.47,47.5 221.49,48.51 249.43,48.51 249.94,48.01 253.75,48.01 256.79,51.05 270,51.05 | 270,51.05 271.27,52.32 E13.4 | v288.54,50.55 288.04,51.05 270,51.05
BUS11  (via drill 0.61)
  Top 0.254: E9.9 332.74,54.61 332.74,59.69 E9.12 | R2.2 294.39,62.99 294.39,55.88 292.35,53.85 R14.1 291.59,53.59 v288.8,56.39 | 270.26,62.99 269.49,62.23 E13.14 | 270.26,62.99 270.26,77.98 269.49,78.74 E12.14 | v64.77,42.16 64.77,39.62 63.75,38.61 J1.14 | v270.26,46.74 270.26,62.99
  Bottom 0.254: E9.12 332.23,59.94 331.47,59.18 324.61,59.18 323.6,60.2 323.6,64.52 295.91,64.52 295.15,63.75 R2.2 | v64.77,42.16 64.77,45.47 74.42,45.47 74.93,44.96 132.84,44.96 134.37,46.48 153.92,46.48 154.94,45.47 176.28,45.47 177.8,46.99 182.63,46.99 183.64,45.97 221.23,45.97 222.25,46.99 240.79,46.99 242.32,45.47 268.99,45.47 v270.26,46.74 | v288.8,56.39 286.51,58.67 271.02,58.67 269.75,59.94 E13.14
BUSEN\  (via drill 0.61)
  Top 0.254: v58.67,51.05 52.07,44.45 52.07,39.62 51.05,38.61 J1.24
  Bottom 0.254: v58.67,51.05 68.07,51.05 73.66,56.64 107.95,56.64 111.25,59.94 E34.13
DEP\  (via drill 0.61)
  Top 0.254: v170.18,49.02 170.18,52.07 E28.5 | v92.46,48.51 72.39,68.58 72.39,78.99 71.37,80.01 67.31,80.01 67.31,81.53 66.29,82.55 57.15,82.55 57.15,80.26 56.13,79.25 J2.20
  Bottom 0.254: v170.18,49.02 169.67,49.53 147.57,49.53 147.07,50.04 120.4,50.04 118.87,48.51 v92.46,48.51
DISP0
  Top 0.254: E36.15 106.93,22.86 108.97,24.89 108.97,31.75 E35.3 108.97,34.29 108.2,35.05 108.2,58.93 108.97,59.69 E34.14 109.47,62.23 112.27,65.02 112.27,70.1 114.05,71.88 114.05,72.39 J4.5
DISP1  (via drill 0.61)
  Top 0.254: 112.78,51.31 112.01,52.07 E34.4 | 112.78,51.31 113.28,50.8 v113.28,31.24 113.28,16 114.05,15.24 E36.5 | 112.78,51.31 112.78,68.58 116.59,72.39 J4.6
  Bottom 0.254: v113.28,31.24 107.95,31.24 107.19,32 E35.2
DISP2  (via drill 0.61)
  Top 0.254: 105.16,30.99 105.66,30.48 105.66,16 106.43,15.24 E36.2 | 105.16,30.99 104.39,31.75 E35.1 | 105.16,30.99 105.16,50.8 106.43,52.07 E34.2 106.93,54.61 107.7,55.37 107.7,66.8 v111.76,70.87
  Bottom 0.254: v111.76,70.87 117.09,70.87 118.87,72.64 J4.7
DISPINH  (via drill 0.61)
  Top 0.254: v243.33,66.04 247.9,70.61 247.9,79.25 248.67,80.01 E16.9 | E22.12 218.19,41.91 217.42,42.67 v217.42,66.29 217.17,66.55 217.17,83.06 v212.34,83.06 | v124.97,91.69 115.82,82.55 115.82,78.74 112.01,74.93 J4.4 | v176.78,82.8 v176.78,89.92
  Bottom 0.254: v217.42,66.29 226.06,66.29 226.31,66.04 v243.33,66.04 | v124.97,91.69 125.98,92.71 173.99,92.71 v176.78,89.92 | v176.78,82.8 177.29,82.3 205.49,82.3 206.25,83.06 v212.34,83.06
DISPLAY0  (via drill 0.61)
  Top 0.254: v249.94,7.87 249.94,10.16 251.21,11.43 E19.7 | v189.23,7.87 180.34,16.76 v180.34,17.02 | v153.92,16.51 150.88,19.56 150.88,57.66 148.34,60.2 148.34,71.63 147.57,72.39 J3.7
  Bottom 0.254: v249.94,7.87 v189.23,7.87 | v180.34,17.02 179.32,18.03 166.62,18.03 165.61,17.02 154.43,17.02 v153.92,16.51
DISPLAY1  (via drill 0.61)
  Top 0.254: v256.79,29.72 256.79,24.13 254.25,21.59 E19.9 | v206.76,29.21 204.22,31.75 204.22,48.26 201.68,50.8 v201.68,79.25 | v178.05,79.76 177.8,80.01 v177.8,86.36 | v144.78,90.68 144.78,82.55 J3.11
  Bottom 0.254: v256.79,29.72 256.29,29.21 v206.76,29.21 | v201.68,79.25 200.66,80.26 178.56,80.26 v178.05,79.76 | v177.8,86.36 173.99,90.17 164.59,90.17 163.58,91.19 145.29,91.19 v144.78,90.68
DISPLAY2  (via drill 0.61)
  Top 0.254: v250.19,49.02 250.19,35.31 251.21,34.29 E18.7 | v234.19,51.05 231.9,53.34 v231.9,71.12 | v160.27,69.6 159.51,68.83 155.45,68.83 v155.45,70.36 | v144.78,70.36 144.78,72.39 J3.6
  Bottom 0.254: v250.19,49.02 248.16,51.05 v234.19,51.05 | v231.9,71.12 208.28,71.12 207.01,69.85 179.32,69.85 178.05,71.12 177.29,71.12 176.78,70.61 167.13,70.61 166.12,69.6 v160.27,69.6 | v155.45,70.36 v144.78,70.36
DSPLTH\  (via drill 0.61)
  Top 0.254: E15.9 281.69,22.86 280.92,23.62 280.92,58.93 281.69,59.69 E13.9 | v313.69,62.48 323.6,72.39 323.6,76.2 327.41,80.01 E8.8
  Bottom 0.254: v313.69,62.48 313.44,62.74 305.56,62.74 304.29,61.47 282.45,61.47 E13.9
E30PIN8  (via drill 0.61)
  Top 0.254: v179.07,43.94 v179.07,22.35 | v223.52,43.94 223.52,52.07 E21.5 223.27,54.61 223.27,55.88 v223.01,56.13 | v220.98,56.9 220.98,59.69 E21.11
  Bottom 0.254: v179.07,22.35 175.77,22.35 E30.8 | v179.07,43.94 179.58,43.43 223.01,43.43 v223.52,43.94 | v220.98,56.9 221.74,56.13 v223.01,56.13
E35-Y4
  Bottom 0.254: E35.11 117.35,41.66 118.11,42.42 135.89,42.42 136.65,41.66 E32.12
EMA0\  (via drill 0.61)
  Top 0.254: R34.2 15.75,12.95 39.12,36.32 42.67,36.32 42.67,37.85 J1.30 43.43,38.61 43.43,39.12 44.45,40.13 44.45,40.89 v45.72,42.16 | v165.86,87.63 165.86,82.8 167.39,81.28 E27.11 | v80.26,64.01 v100.84,84.58
  Bottom 0.254: v165.86,87.63 165.35,88.14 161.04,88.14 160.02,89.15 146.81,89.15 145.8,88.14 137.16,88.14 133.6,84.58 v100.84,84.58 | v80.26,64.01 68.33,52.07 55.63,52.07 v45.72,42.16
EMA1\  (via drill 0.61)
  Top 0.254: 45.21,33.53 45.21,37.85 J1.28 | 45.21,33.53 45.21,12.95 18.29,12.95 R35.2 | v168.91,86.61 168.91,86.11 171.7,83.31 171.7,82.04 172.47,81.28 E27.9 | v137.41,87.12 121.16,87.12 121.16,85.34 117.86,82.04 117.86,79.5 112.78,74.42 112.78,72.39 112.27,71.88 v102.62,71.88 | v52.83,70.61 49.53,67.31 49.53,37.85 45.21,33.53
  Bottom 0.254: v168.91,86.61 161.8,86.61 159.77,88.65 147.07,88.65 145.54,87.12 v137.41,87.12 | v102.62,71.88 100.58,73.91 56.13,73.91 v52.83,70.61
EMA2\  (via drill 0.61)
  Top 0.254: R36.2 13.21,12.95 37.08,36.83 40.13,36.83 40.13,37.85 J1.32 | v162.56,89.66 162.56,81.28 E27.13 | v106.17,85.6 94.23,73.66 94.23,49.02 87.12,41.91 80.77,41.91 v80.77,38.61
  Bottom 0.254: v162.56,89.66 162.05,90.17 146.3,90.17 145.29,89.15 115.32,89.15 111.76,85.6 v106.17,85.6 | v80.77,38.61 78.99,36.83 42.16,36.83 41.15,37.85 J1.32
EMODE\  (via drill 0.61)
  Top 0.254: 382.52,30.99 382.52,14.73 383.29,13.97 E3.6 | 382.52,30.99 383.29,31.75 E2.6 | 382.52,30.99 382.52,51.31 383.29,52.07 E1.6 383.29,54.61 379.48,58.42 379.48,70.61 366.27,83.82 361.7,83.82 361.7,80.01 361.19,79.5 349,79.5 349,82.55 347.98,83.57 277.11,83.57 v275.34,81.79 | v230.89,77.22 230.89,66.04 227.08,62.23 227.08,35.05 226.31,34.29 E22.6
  Bottom 0.254: v230.89,77.22 232.41,78.74 249.43,78.74 250.95,80.26 E16.8 251.97,82.3 274.83,82.3 v275.34,81.79
ENT0  (via drill 0.61)
  Top 0.254: E7.13 350.27,19.05 349.5,18.29 349.5,10.41 331.98,10.41 330.71,11.68 E11.8 329.95,13.97 329.18,14.73 329.18,22.1 324.61,22.1 323.6,21.08 323.6,10.16 293.88,10.16 292.86,11.18 271.78,11.18 268.22,7.62 268.22,5.33 204.47,5.33 196.6,13.21 196.6,22.86 194.56,24.89 194.56,41.4 189.48,46.48 189.48,57.4 v189.99,57.91 | v112.78,11.18 112.78,17.02 109.47,20.32 E36.14 | v157.23,6.35 164.08,13.21 164.08,27.18 168.66,31.75 168.66,47.5 167.89,48.26 167.89,51.31 168.66,52.07 168.66,56.64 v169.93,57.91
  Bottom 0.254: E3.13 372.87,19.3 371.35,17.78 352.55,17.78 351.03,19.3 E7.13 | v112.78,11.18 116.33,7.62 129.29,7.62 130.56,6.35 v157.23,6.35 | v189.99,57.91 v169.93,57.91
ENT1  (via drill 0.61)
  Top 0.254: v226.06,10.41 227.58,11.94 227.58,14.99 232.66,20.07 v232.66,20.57 | v329.44,27.18 329.95,27.69 329.95,31.75 E10.8 330.45,34.29 330.45,35.31 v331.72,36.58
  Bottom 0.254: E2.13 372.87,39.62 371.35,38.1 352.55,38.1 351.03,39.62 E6.13 350.01,39.62 346.96,36.58 v331.72,36.58 | v226.06,10.41 222,10.41 221.74,10.67 213.11,10.67 212.09,11.68 177.04,11.68 176.28,10.92 114.3,10.92 112.27,12.95 E36.4 | v232.66,20.57 239.27,27.18 v329.44,27.18
ENT2  (via drill 0.61)
  Top 0.254: v147.32,16.51 149.86,19.05 v149.86,45.47 | v326.9,49.53 329.69,52.32 E9.8 330.45,54.61 330.45,56.13 v331.72,57.4
  Bottom 0.254: E1.13 372.87,59.94 371.35,58.42 352.55,58.42 351.03,59.94 E5.13 350.01,59.94 347.47,57.4 v331.72,57.4 | v147.32,16.51 100.33,16.51 100.33,14.73 102.87,12.19 107.95,12.19 108.71,12.95 E36.3 | v149.86,45.47 150.37,44.96 176.53,44.96 178.05,46.48 180.09,46.48 181.1,45.47 221.49,45.47 222.5,46.48 224.54,46.48 226.06,44.96 274.32,44.96 278.89,49.53 v326.9,49.53
FUN\  (via drill 0.61)
  Top 0.254: v192.53,37.59 192.53,36.07 190.75,34.29 E25.2 | v151.13,83.57 156.21,78.49 v156.21,77.72 | v191.77,76.96 192.02,76.71 192.02,55.88 192.79,55.12 192.79,54.61 E24.3 193.29,52.07 193.29,43.94 195.33,41.91 E25.11
  Bottom 0.254: v192.53,37.59 194.56,39.62 195.07,39.62 E25.11 | v151.13,83.57 108.46,83.57 107.19,82.3 J4.15 | v156.21,77.72 157.23,76.71 191.52,76.71 v191.77,76.96
GATEENT\  (via drill 0.61)
  Top 0.254: E11.1 312.17,13.97 311.4,14.73 311.4,30.99 312.17,31.75 E10.1 312.67,34.29 313.44,35.05 313.44,51.31 312.67,52.07 E9.1 | v218.95,16 222.5,19.56 v222.5,27.69 222.5,29.72 225.04,32.26 225.04,51.31 225.81,52.07 E21.6
  Bottom 0.254: v218.95,16 215.14,16 213.87,17.27 185.67,17.27 184.4,16 171.7,16 170.69,14.99 E30.5 | v222.5,27.69 278.89,27.69 282.7,31.5 311.4,31.5 311.91,32 E10.1
GATESR\  (via drill 0.61)
  Top 0.254: E11.19 314.71,21.59 313.94,22.35 313.94,38.61 314.71,39.37 E10.19 314.71,41.91 313.94,42.67 313.94,58.93 314.71,59.69 E9.19 315.21,62.23 315.21,62.74 v318.52,66.04 | v139.7,49.02 139.7,41.91 E32.11 | v137.67,49.02 138.18,49.53 138.18,57.15 141.22,60.2 141.22,70.61 142.49,71.88 143.76,71.88 143.76,74.93 144.78,75.95 153.42,75.95 v153.42,74.68 | v186.18,73.91 188.98,71.12 v188.98,70.87 | v193.04,70.87 199.39,77.22 v199.39,85.34 | v262.38,87.38 265.68,84.07 265.68,78.49 267.72,76.45 267.72,68.58 v267.21,68.07
  Bottom 0.254: v137.67,49.02 v139.7,49.02 | v153.42,74.68 153.67,74.93 185.17,74.93 v186.18,73.91 | v188.98,70.87 v193.04,70.87 | v199.39,85.34 201.42,87.38 v262.38,87.38 | v267.21,68.07 316.48,68.07 v318.52,66.04
GND  (via drill 0.61)
  Top 0.508: C7.1 340.11,14.73 336.55,18.29 336.55,30.73 335.53,31.75 E10.10 | C6.1 340.11,35.05 338.33,36.83 338.33,49.28 335.53,52.07 E9.10 335.53,54.61 338.33,57.4 338.33,72.39 340.11,74.17 C4.1 | E1.3 376.43,52.32 377.95,52.32 E1.4 378.97,52.32 380.49,52.32 E1.5 | E3.3 376.43,11.68 377.95,11.68 E3.4 378.97,11.68 380.49,11.68 E3.5 380.75,13.97 379.73,14.99 379.73,32 | E6.8 361.19,34.04 367.54,34.04 C2.1 | E2.3 376.43,32 377.95,32 E2.4 378.97,32 379.73,32 | 379.73,32 380.49,32 E2.5 | E4.8 360.43,72.39 359.41,71.37 359.41,55.63 360.43,54.61 E5.8 | 289.31,24.89 289.31,29.97 R19.1 | 289.31,24.89 289.31,23.37 R24.1 | 294.39,25.4 294.39,29.97 R20.1 | 294.39,25.4 294.39,24.89 | 294.39,24.89 294.39,23.37 R23.1 | 294.39,25.4 299.21,30.23 R18.1 | 294.39,24.89 289.31,24.89 | E14.8 282.19,31.75 283.21,30.73 283.21,16.26 282.19,15.24 E15.8 | C11.1 309.63,14.73 308.61,15.75 308.61,26.42 305.05,29.97 R17.1 305.31,30.73 309.12,34.54 C10.1 309.63,35.05 308.61,36.07 308.61,56.13 308.74,56.26 | 308.74,56.26 309.63,55.37 C9.1 | 308.74,56.26 308.61,56.39 308.61,73.15 309.63,74.17 C8.1 | E20.7 228.85,74.93 229.87,75.95 229.87,77.72 230.38,78.23 233.43,78.23 233.43,75.69 C16.1 | C12.1 261.37,72.9 259.08,70.61 259.08,57.66 261.37,55.37 C13.1 261.37,53.85 260.6,53.09 260.6,40.13 260.35,39.88 260.35,32.77 260.48,32.64 | v236.73,37.59 236.47,37.34 236.47,34.29 E18.1 235.97,31.75 234.95,30.73 234.95,13.72 | 260.48,32.64 261.37,33.53 C14.1 | 260.48,32.64 260.35,32.51 260.35,17.02 261.37,16 C15.1 | E23.7 229.11,13.72 232.92,13.72 C19.1 234.44,13.72 234.95,13.72 | 234.95,13.72 235.71,13.72 E19.1 236.47,13.97 236.47,17.27 v236.73,17.53
  Top 0.508: v197.61,16.26 197.61,20.07 197.87,20.32 E26.12 | R2.1 294.89,53.85 295.91,54.86 295.91,64.01 288.54,71.37 282.45,71.37 E12.8 | 205.36,56.52 205.49,56.64 205.49,71.12 209.04,74.68 210.06,74.68 C20.1 | 205.36,56.52 203.45,54.61 E24.7 203.2,52.07 v203.2,50.55 | v185.42,50.55 185.42,53.85 C24.1 | E17.15 238.51,59.69 236.47,57.66 236.47,54.61 E17.1 | E33.7 146.81,13.72 146.05,14.48 144.02,14.48 143.51,13.97 143.51,11.43 145.03,9.91 156.72,9.91 156.72,14.99 C30.1 157.73,16 158.75,17.02 158.75,22.86 157.73,23.88 157.73,33.53 C29.1 | 209.68,35.94 210.57,35.05 C22.1 | 209.68,35.94 209.55,36.07 209.55,52.83 210.57,53.85 C21.1 | v205.74,56.13 205.49,56.39 205.36,56.52 | C38.- 11.18,80.77 14.22,80.77 C39.- | J2.15 60.71,80.77 60.71,79.25 J2.16 60.96,78.23 60.96,41.15 J1.15 | J2.15 61.47,81.03 62.99,81.03 J2.13 64.01,81.03 65.53,81.03 J2.11 | J2.39 30.99,81.03 32.51,81.03 J2.37 33.53,81.03 35.05,81.03 J2.35 36.07,81.03 37.59,81.03 J2.33 38.61,81.03 40.13,81.03 J2.31 41.15,81.03 42.67,81.03 J2.29 43.69,81.03 45.21,81.03 J2.27 | J2.23 51.31,81.03 52.83,81.03 J2.21 53.85,81.03 55.37,81.03 J2.19 | J2.15 60.45,81.03 58.93,81.03 J2.17 | J1.39 30.99,40.39 32.51,40.39 J1.37 33.53,40.39 35.05,40.39 J1.35 36.07,40.39 37.59,40.39 J1.33 38.61,40.39 40.13,40.39 J1.31 41.15,40.39 42.67,40.39 J1.29 | J1.25 47.75,40.39 46.23,40.39 J1.27 | J1.19 55.37,40.39 53.85,40.39 J1.21 | 100.33,25.65 100.33,32.51 101.35,33.53 C35.1 101.85,35.05 102.87,36.07 102.87,52.83 101.85,53.85 C34.1 | 100.33,25.65 100.33,17.02 101.35,16 C36.1 | E35.8 121.67,31.75 120.65,30.73 120.65,16.26 121.67,15.24 E36.8
  Top 0.508: J4.8 122.17,72.39 123.19,71.37 123.19,56.9 122.17,55.88 122.17,54.61 E34.8 | v153.16,54.36 153.16,69.34 150.11,72.39 J3.8 | 100.33,25.65 79.25,25.65 67.31,37.59 67.31,39.12 66.29,40.13 J1.11 | E32.7 147.57,34.29 148.84,35.56 148.84,49.02 149.86,50.04 149.86,52.07 E31.8 | C23.1 210.57,14.73 209.55,15.75 209.55,35.81 209.68,35.94
  Bottom 0.508: C5.1 339.6,54.36 335.79,54.36 E9.10 334.77,54.36 334.01,55.12 319.28,55.12 318.77,54.61 318.77,51.56 311.66,51.56 308.86,54.36 | E11.10 335.79,13.72 339.6,13.72 C7.1 | E10.10 335.79,34.04 339.6,34.04 C6.1 | E8.7 328.17,74.68 339.6,74.68 C4.1 340.87,75.44 359.41,75.44 360.17,74.68 E4.8 | E5.8 361.19,54.36 367.54,54.36 C1.1 369.06,54.86 369.32,55.12 374.65,55.12 375.41,54.36 E1.3 | 384.81,51.56 385.57,52.32 E1.7 | 384.81,51.56 382.27,51.56 381.51,52.32 E1.5 | E7.8 361.19,13.72 367.54,13.72 C3.1 369.06,14.22 369.32,14.48 374.65,14.48 375.41,13.72 E3.3 | E3.7 385.57,11.68 384.81,10.92 382.27,10.92 381.51,11.68 E3.5 | E2.5 381.51,32 382.27,31.24 384.81,31.24 385.57,32 E2.7 385.83,34.29 384.81,34.29 384.81,51.56 | C2.1 369.06,34.54 369.32,34.8 374.65,34.8 375.41,34.04 E2.3 | R17.1 304.29,30.23 303.28,29.21 301.24,29.21 300.23,30.23 R18.1 | C11.1 309.12,13.72 306.07,13.72 305.31,12.95 R21.1 304.29,12.45 303.28,11.43 301.24,11.43 300.23,12.45 R22.1 299.21,12.95 298.2,13.97 282.45,13.97 E15.8 | 288.16,54.48 289.05,53.59 R1.1 | 288.16,54.48 288.04,54.61 282.7,54.61 282.45,54.36 E13.8 | 293.24,54.48 293.12,54.61 288.29,54.61 288.16,54.48 | 293.24,54.48 294.13,53.59 R2.1 | 293.24,54.48 293.37,54.61 298.2,54.61 299.21,53.59 R4.1 300.23,53.59 301.24,54.61 303.28,54.61 304.29,53.59 R3.1 305.31,53.59 306.07,54.36 308.86,54.36 | 308.86,54.36 309.12,54.36 C9.1 | E17.8 254.51,54.36 260.86,54.36 C13.1 | E12.8 281.43,73.41 279.91,74.93 262.89,74.93 262.13,74.17 C12.1 260.86,73.41 251.97,73.41 E16.7 250.95,74.68 250.19,75.44 234.7,75.44 234.44,75.18 C16.1 | E19.8 254.51,13.72 255.78,14.99 260.86,14.99 C15.1
  Bottom 0.508: C14.1 260.86,34.04 254.51,34.04 E18.8 253.49,32 252.73,31.24 237.49,31.24 236.73,32 E18.1 235.71,34.04 234.44,34.04 C18.1 232.92,34.04 229.11,34.04 E22.7 | v236.73,37.59 238.51,39.37 E18.15 | v236.73,17.53 236.98,17.53 238.51,19.05 E19.15 | E30.7 175.77,14.99 184.66,14.99 C26.1 185.93,15.75 197.1,15.75 v197.61,16.26 197.87,16 208.28,16 210.06,14.22 C23.1 211.33,14.48 227.33,14.48 228.09,13.72 E23.7 | E28.8 178.31,54.36 184.66,54.36 C24.1 | v185.42,50.55 185.67,50.8 202.95,50.8 v203.2,50.55 | E17.1 235.71,54.36 234.44,54.36 C17.1 232.92,54.36 229.11,54.36 E21.7 228.09,54.36 227.33,55.12 211.84,55.12 211.58,54.86 C21.1 210.06,54.86 207.01,54.86 v205.74,56.13 | C22.1 210.06,34.04 203.71,34.04 E25.7 202.69,34.04 201.93,34.8 195.33,34.8 | E32.7 147.83,34.04 156.72,34.04 C29.1 157.99,34.8 176.53,34.8 177.29,34.04 E29.8 178.31,34.04 184.66,34.04 C25.1 185.93,34.8 192.79,34.8 | 195.33,34.8 192.79,34.8 | J2.27 46.23,81.03 47.75,81.03 J2.25 48.77,81.03 50.29,81.03 J2.23 | J2.17 57.91,81.03 56.39,81.03 J2.19 | C39.- 16.26,81.79 17.27,82.8 28.7,82.8 29.97,81.53 J2.39 | 6.86,24.13 5.84,23.11 R27.2 | 6.86,24.13 10.92,24.13 11.94,25.15 R30.2 | 6.86,24.13 6.86,38.86 GND.1 9.4,41.4 10.16,42.16 28.7,42.16 29.97,40.89 J1.39 | J1.27 45.21,40.39 43.69,40.39 J1.29 | J1.25 48.77,40.39 50.29,40.39 J1.23 51.31,40.39 52.83,40.39 J1.21 | J1.19 56.39,40.39 57.91,40.39 J1.17 58.93,40.39 60.45,40.39 J1.15 61.47,40.39 62.99,40.39 J1.13 64.01,40.39 65.53,40.39 J1.11 | E35.8 122.43,34.04 128.78,34.04 C32.1 | C33.1 128.78,13.72 122.43,13.72 E36.8 121.41,14.99 120.65,15.75 102.11,15.75 C36.1
  Bottom 0.508: J3.8 150.37,73.41 156.72,73.41 C27.1 157.99,74.17 173.99,74.17 174.75,73.41 E27.7 | C28.1 156.72,54.36 v153.16,54.36 150.37,54.36 E31.8 149.35,54.36 148.59,55.12 130.05,55.12 C31.1 128.78,54.36 122.43,54.36 E34.8 121.41,54.36 119.89,55.88 103.38,55.88 102.36,54.86 C34.1 | 192.79,34.8 192.79,34.29 E25.3 | 195.33,34.8 195.33,34.29 E25.4
  pour Top (isolate 0.254): 0,0 0,93.98 393.7,93.98 393.7,0
IND1\  (via drill 0.61)
  Top 0.254: v86.36,53.34 71.37,68.33 71.37,78.23 J2.8 | v139.19,29.72 138.68,29.21 138.68,19.05 140.72,17.02 140.72,4.32 161.54,4.32 169.16,11.94 169.16,15.24 171.2,17.27 171.2,29.97 171.45,30.23 171.45,57.4 174.75,57.4 175.51,56.64 175.51,54.61 E28.7 | v112.27,30.23 110.24,32.26 110.24,50.8 109.47,51.56 109.47,52.07 E34.3
  Bottom 0.254: v86.36,53.34 102.87,53.34 102.87,54.36 103.63,55.12 107.95,55.12 108.71,54.36 E34.3 | v139.19,29.72 138.68,30.23 v112.27,30.23
IND2\  (via drill 0.61)
  Top 0.254: v93.22,49.53 76.45,66.29 76.45,78.23 J2.4
  Bottom 0.254: v93.22,49.53 119.13,49.53 119.13,51.31 118.36,52.07 118.36,54.1 117.35,55.12 115.57,55.12 114.81,54.36 E34.5
INIT\  (via drill 0.61)
  Top 0.254: v143.76,57.66 145.8,59.69 145.8,75.44 147.83,75.44 148.84,74.42 148.84,62.99 149.61,62.23 E31.9 | v38.35,71.63 38.35,78.23 J2.34
  Bottom 0.254: v143.76,57.66 117.86,57.66 115.32,60.2 115.32,63.5 82.04,63.5 80.01,65.53 44.45,65.53 v38.35,71.63
KEY-F\  (via drill 0.61)
  Top 0.254: 195.33,19.81 195.33,20.32 E26.13 | 195.33,19.81 195.33,15.24 E26.4 | v130.56,72.39 v130.56,67.31 | v169.93,67.56 170.18,67.82 170.18,71.12 E27.5 | 195.33,19.81 186.69,19.81 186.69,22.35 182.63,26.42 182.63,56.13 183.13,56.64 183.13,63.75 181.1,65.79 v181.1,67.06
  Bottom 0.254: v130.56,72.39 127.51,75.44 110.49,75.44 109.73,74.68 J4.3 | v130.56,67.31 151.64,67.31 151.89,67.56 v169.93,67.56 170.18,67.31 170.43,67.06 v181.1,67.06
KEYCNTL\  (via drill 0.61)
  Top 0.254: v137.16,68.83 137.16,64.52 139.45,62.23 E31.13 | v68.58,68.58 68.58,78.23 J2.10
  Bottom 0.254: v137.16,68.83 136.65,68.33 131.57,68.33 131.06,68.83 118.87,68.83 117.09,67.06 83.06,67.06 82.55,67.56 80.01,67.56 78.99,68.58 v68.58,68.58
KEYSTB  (via drill 0.61)
  Top 0.254: v191.26,55.37 191.52,55.63 191.52,75.18 v191.01,75.69
  Bottom 0.254: v191.26,55.37 189.48,55.37 188.47,54.36 E24.1 | J4.2 107.19,74.68 108.71,76.2 190.5,76.2 v191.01,75.69 191.26,75.95 192.02,75.95 192.28,76.2 293.88,76.2 298.2,71.88 321.31,71.88 322.07,72.64 E8.5
KEYSTB\  (via drill 0.61)
  Top 0.254: v242.32,50.04 242.32,78.74 243.59,80.01 E16.11 | v140.72,51.56 140.72,22.35 139.95,21.59 E33.11
  Bottom 0.254: E33.11 140.21,19.3 140.97,18.54 143.51,18.54 144.27,19.3 E33.9 | 189.23,51.56 v140.72,51.56 133.35,51.56 132.59,52.32 E31.1 | 189.23,51.56 189.99,52.32 E24.2 | 214.63,51.56 215.39,52.32 E21.2 | 214.63,51.56 189.23,51.56 | v242.32,50.04 229.36,50.04 227.84,51.56 214.63,51.56
KFUN0\  (via drill 0.61)
  Top 0.254: E3.2 372.87,11.68 371.35,11.68 E3.1 370.33,11.68 370.33,8.89 294.39,8.89 292.61,10.67 272.03,10.67 268.73,7.37 268.73,4.83 197.1,4.83 192.02,9.91 192.02,11.43 190.75,12.7 E26.2 190.25,15.24 190.25,15.75 188.21,15.75 180.09,23.88 180.09,26.92 181.1,27.94 v181.1,59.18 | v140.21,65.79 140.21,69.6 137.41,72.39 J3.3 | v168.91,59.44 v168.91,65.53
  Bottom 0.254: v140.21,65.79 140.72,66.29 167.13,66.29 167.39,66.55 167.89,66.55 v168.91,65.53 | v168.91,59.44 169.16,59.18 v181.1,59.18
KFUN1\  (via drill 0.61)
  Top 0.254: v193.04,10.16 193.04,12.7 E26.3 | v131.06,8.38 126.24,13.21 126.24,78.49 129.29,81.53 130.56,81.53 130.56,78.74 134.37,74.93 J3.2 | v362.71,9.91 362.71,23.88 370.59,31.75 E2.1
  Bottom 0.254: E2.1 371.35,32 372.87,32 E2.2 | v131.06,8.38 171.7,8.38 171.96,8.13 173.23,8.13 173.74,8.64 175.51,8.64 177.55,10.67 192.53,10.67 v193.04,10.16 193.29,9.91 193.55,9.65 203.45,9.65 203.96,10.16 213.11,10.16 214.38,8.89 266.7,8.89 268.48,10.67 274.83,10.67 275.08,10.41 362.2,10.41 v362.71,9.91
KFUN2\  (via drill 0.61)
  Top 0.254: E1.2 372.87,52.32 371.35,52.32 E1.1 370.59,52.07 369.57,51.05 369.57,33.78 v362.97,27.18 | v244.35,25.4 242.32,23.37 242.32,9.4 240.54,7.62 204.22,7.62 | 204.22,7.62 202.95,7.62 202.95,9.65 200.91,11.68 200.91,12.7 E26.6 | v131.32,38.61 132.33,38.61 133.1,39.37 133.1,62.23 131.83,63.5 131.83,72.39 J3.1 | v127.76,36.83 127.51,36.58 127.51,22.86 v129.54,20.83 | v183.39,19.05 186.94,15.49 186.94,12.7 v192.79,6.86 | 204.22,7.62 v204.22,6.86
  Bottom 0.254: v362.97,27.18 361.19,25.4 v244.35,25.4 | v131.32,38.61 131.32,39.12 130.81,39.62 130.81,40.64 129.03,40.64 127.25,38.86 127.25,36.83 v127.76,36.83 | v129.54,20.83 131.06,19.3 131.06,18.03 152.15,18.03 153.67,19.56 156.46,19.56 156.97,19.05 164.34,19.05 164.85,19.56 173.23,19.56 173.74,19.05 v183.39,19.05 | v204.22,6.86 v192.79,6.86
LAENAB\  (via drill 0.61)
  Top 0.254: v212.85,9.14 215.39,11.68 E23.2 | v189.23,9.14 182.12,16.26 v182.12,17.53 | v80.01,17.53 59.69,37.85 59.69,67.56 53.59,73.66 53.59,78.23 J2.22
  Bottom 0.254: v189.23,9.14 v212.85,9.14 | v182.12,17.53 181.1,18.54 166.37,18.54 165.35,17.53 v80.01,17.53
LDSR  (via drill 0.61)
  Top 0.254: E7.9 360.43,21.59 359.66,22.35 359.66,38.61 360.43,39.37 E6.9 360.93,41.91 361.7,42.67 361.7,62.99 | v193.55,89.92 187.96,84.33 187.96,77.72 175.26,77.72 173.74,79.25 173.74,82.04 171.96,83.82 171.96,91.19 154.69,91.19 148.84,85.34 148.84,79.5 140.72,79.5 136.14,74.93 136.14,58.42 135.64,57.91 135.64,22.35 134.87,21.59 E33.13 | v360.43,76.2 361.7,74.93 361.7,62.99 | 361.7,62.99 360.93,62.23 E5.9
  Bottom 0.254: v193.55,89.92 194.56,90.93 264.41,90.93 272.03,83.31 277.11,83.31 277.88,84.07 334.52,84.07 342.39,76.2 v360.43,76.2
MAEN\  (via drill 0.61)
  Top 0.254: v235.2,88.39 235.2,40.89 233.43,40.89 232.41,39.88 232.41,25.15 228.85,21.59 E23.8 | v180.59,78.74 v189.74,87.88 | v161.54,78.23 161.04,78.74 v161.04,86.11 | v149.1,87.63 144.02,92.71 99.57,92.71 99.57,85.34 90.68,76.45 81.53,76.45 v81.53,77.47
  Bottom 0.254: v235.2,88.39 234.7,87.88 v189.74,87.88 | v180.59,78.74 180.09,78.23 v161.54,78.23 | v161.04,86.11 159.51,87.63 v149.1,87.63 | v81.53,77.47 78.99,80.01 42.16,80.01 41.15,78.99 J2.32
MALC\  (via drill 0.61)
  Top 0.254: v159,69.85 159,70.61 163.58,70.61 164.59,69.6 164.59,64.52 166.12,62.99 166.12,58.42 169.16,58.42 169.67,58.93 171.2,58.93 172.21,59.94 E28.11 | v135.13,70.36 135.64,70.87 135.64,75.44 131.06,80.01 131.06,82.55 130.56,83.06 120.4,83.06 120.4,80.01 v117.6,77.22 | v37.34,75.44 35.81,76.96 35.81,78.23 J2.36
  Bottom 0.254: v159,69.85 158.5,69.34 152.65,69.34 152.4,69.6 145.29,69.6 145.03,69.34 138.94,69.34 137.92,70.36 v135.13,70.36 | v117.6,77.22 117.09,76.71 85.85,76.71 84.58,75.44 v37.34,75.44
MCLOCK\  (via drill 0.61)
  Top 0.254: v127.25,70.36 126.75,69.85 126.75,17.78 130.05,17.78 134.11,13.72 E33.2
  Bottom 0.254: v127.25,70.36 126.75,69.85 107.44,69.85 104.65,72.64 J4.1
MD\  (via drill 0.61)
  Top 0.254: v120.4,66.8 120.4,55.37 119.63,54.61 E34.7 | v59.94,68.58 58.67,69.85 58.67,78.23 J2.18
  Bottom 0.254: v120.4,66.8 119.89,66.29 117.86,66.29 117.6,66.04 82.04,66.04 81.53,66.55 61.98,66.55 v59.94,68.58
MEMSTART\  (via drill 0.61)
